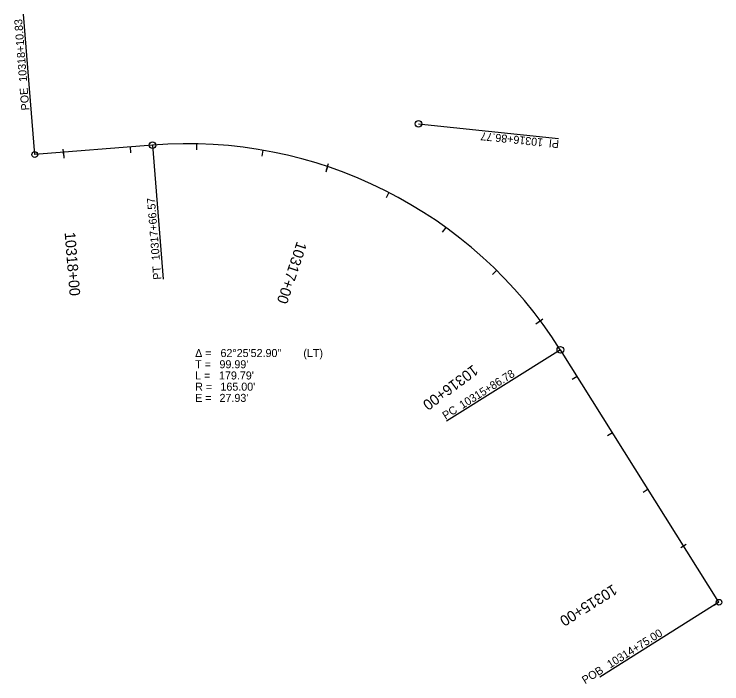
# Model space of a CAD drawing. Extents: x 14284759 to 14285025, y 8637453 to 8637704.
import ezdxf

# ---------------------------------------------------------------- set-up
doc = ezdxf.new("R2010")
doc.units = 0
for name, color, linetype in [('Contours Minor', 7, 'Continuous'), ('SurBreakLine', 7, 'Continuous'), ('SurTerrainIsland', 7, 'Continuous'), ('SurTerrainThematicHeight', 7, 'Continuous')]:
    doc.layers.add(name, color=color, linetype=linetype)

msp = doc.modelspace()

# ---------------------------------------------------------------- linework, layer by layer
at = {"layer": 'Contours Minor'}
for p, q in [((14284811.14, 8637654.95), (14284767.02, 8637651.42)), ((14285023.47, 8637483.6), (14284964.01, 8637578.25))]:
    msp.add_line(p, q, dxfattribs=at)
msp.add_arc((14284824.29, 8637490.47), 165, 32.1391, 94.5705, dxfattribs=at)
msp.add_arc((14284824.29, 8637490.47), 165, 32.1391, 94.5705, dxfattribs=at)
at = {"layer": 'SurBreakLine'}
for p, q in [((14284827.7, 8637655.44), (14284827.65, 8637653.25)), ((14284777.91, 8637651.06), (14284777.72, 8637653.5)), ((14284802.74, 8637654.28), (14284802.91, 8637652.1)), ((14284852.56, 8637653.03), (14284852.18, 8637650.88)), ((14284876.38, 8637645.74), (14284877.16, 8637648.07)), ((14284899.78, 8637637.19), (14284898.78, 8637635.25)), ((14284921.06, 8637624.12), (14284919.78, 8637622.35)), ((14284940.12, 8637607.98), (14284938.59, 8637606.43)), ((14284955.55, 8637588.42), (14284957.51, 8637589.88)), ((14284970.27, 8637568.28), (14284968.42, 8637567.11)), ((14284983.57, 8637547.11), (14284981.72, 8637545.95)), ((14284996.87, 8637525.94), (14284995.02, 8637524.78)), ((14285009.13, 8637504.12), (14285011.21, 8637505.42)), ((14285023.47, 8637483.6), (14285021.62, 8637482.44))]:
    msp.add_line(p, q, dxfattribs=at)
at = {"layer": 'SurTerrainIsland'}
for p, q in [((14284767.02, 8637651.42), (14284762.81, 8637704.05)), ((14284762.81, 8637704.05), (14284762.81, 8637704.05)), ((14284910.82, 8637662.91), (14284963.33, 8637657.46)), ((14284811.14, 8637654.95), (14284815.16, 8637604.71)), ((14284963.33, 8637657.46), (14284963.33, 8637657.46)), ((14284815.16, 8637604.71), (14284815.16, 8637604.71)), ((14284964.01, 8637578.25), (14284921.33, 8637551.44)), ((14284921.33, 8637551.44), (14284921.33, 8637551.44)), ((14285023.47, 8637483.6), (14284978.76, 8637455.51)), ((14284978.76, 8637455.51), (14284978.76, 8637455.51))]:
    msp.add_line(p, q, dxfattribs=at)
for centre, radius in [((14284910.82, 8637662.91), 1.25), ((14284811.14, 8637654.95), 1.25), ((14284767.02, 8637651.42), 1.07), ((14284964.01, 8637578.25), 1.25), ((14285023.47, 8637483.6), 1.07)]:
    msp.add_circle(centre, radius, dxfattribs=at)
at = {"layer": 'SurTerrainThematicHeight'}
for p, q in [((14284777.82, 8637652.28), (14284777.99, 8637650.11)), ((14284876.77, 8637646.9), (14284876.07, 8637644.83)), ((14284956.53, 8637589.15), (14284954.78, 8637587.85)), ((14285009.13, 8637504.12), (14285011.21, 8637505.42))]:
    msp.add_line(p, q, dxfattribs=at)

# ---------------------------------------------------------------- texts
at = {"layer": 'SurBreakLine'}
for s, rotation, p in [('10318+00', 274.5705, (14284778.21, 8637622.22)), ('10317+00', 251.4558, (14284865.33, 8637619.1)), ('10316+00', 216.7311, (14284931.29, 8637572.82)), ('10315+00', 212.1391, (14284983.7, 8637490.51))]:
    msp.add_text(s, height=4.008, rotation=rotation, dxfattribs=at).set_placement(p)
at = {"layer": 'SurTerrainIsland'}
for s, rotation, p in [('10318+10.83', 94.5705, (14284764.17, 8637678.84)), ('POE ', 94.5705, (14284765.02, 8637668.11)), ('10316+86.77', 174.0717, (14284957.69, 8637657.39)), ('PI ', 174.0717, (14284963.64, 8637656.77)), ('10317+66.57', 94.5705, (14284813.93, 8637611.89)), ('PT', 94.5705, (14284814.5, 8637604.66)), ('10315+86.78', 32.1391, (14284927.31, 8637555.97)), ('PC', 32.1391, (14284920.98, 8637551.99)), ('10314+75.00', 32.1391, (14284982.67, 8637458.75)), ('POB ', 32.1391, (14284973.28, 8637452.85))]:
    msp.add_text(s, height=3, rotation=rotation, dxfattribs=at).set_placement(p)
for s, p in [('Δ = ', (14284827.15, 8637575.52)), ('62°25\'52.90"', (14284836.65, 8637575.52)), (' (LT)', (14284866.59, 8637575.52)), ('T = ', (14284827.15, 8637571.32)), ("99.99'", (14284836.27, 8637571.32)), ('L = ', (14284827.15, 8637567.12)), ("179.79'", (14284836.09, 8637567.12)), ('R = ', (14284827.15, 8637562.92)), ("165.00'", (14284836.63, 8637562.92)), ('E = ', (14284827.15, 8637558.72)), ("27.93'", (14284836.28, 8637558.72))]:
    msp.add_text(s, height=3, dxfattribs=at).set_placement(p)
at = {"layer": 'SurTerrainThematicHeight'}
msp.add_text('10315+00', height=4.008, rotation=212.1391, dxfattribs=at).set_placement((14284983.7, 8637490.51))

doc.saveas('drawing.dxf')
